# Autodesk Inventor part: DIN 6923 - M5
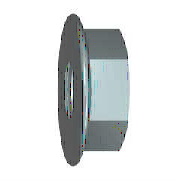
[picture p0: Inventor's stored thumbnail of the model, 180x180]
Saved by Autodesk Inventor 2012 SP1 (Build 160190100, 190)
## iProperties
Created: 2006-02
Part Number: DIN 6923 - M5
Material: Steel, Mild
Description: Hex Nut
Document SubType Name: Modeling
Standard: DIN 6923
Standards Organization: DIN
Language: en-US
Size Designation: M5
Categories: <MemberInstance><Categories><Category DisplayName="Fasteners" InternalName="e4da775c-781d-43d5-af7c-5136215cf5a6" Mnemonic="FSTN"><Category DisplayName="Nuts" I
Mass: 2.39626 g
Surface Area: 3.69972 cm^2
Volume: 0.304867 cm^3
Density: 7.86 g/cm^3
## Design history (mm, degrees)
workaxis "Work Axis1"
workplane "Work Plane1"
revolve "Ring" stored, may be unused: angle "d8" = 90 deg
sketch "Sketch2"
  geometry: L1 (-4, -2.309)-(-4, 2.309); L2 (-4, 2.309)-(0, 4.619); L3 (0, 4.619)-(4, 2.309); L4 (4, 2.309)-(4, -2.309); L5 (4, -2.309)-(0, -4.619); L6 (0, -4.619)-(-4, -2.309); C1 r 4.9 at (0, 0); C2 r 4.9 at (0, 0) reference; 1 further point
  constraints: 12 end point, 1 centre point, 1 coincident, 1 vertical, 11 other
  dimensions: "d6" = 9.2376 distance of L5.end L2.end (= 1.1547 x SW)
extrude "Body" join sketch "Sketch2" distance "d7" = 5 (= KOH); taper "d9" = 0 deg
revolve "Chamfer1" stored, may be unused: angle "d24" = 90 deg
sketch "Sketch4"
  geometry: C1 r 4.9 at (0, 0) reference; 1 further point
  constraints: 1 coincident
hole "Thread" sketch "Sketch4" diameter "d25" = 4.134; stored, may be unused: countersink angle "d29" = 82 deg, drill point angle "d31" = 118 deg; dims "d26" = 6, "d27" = 4, "d28" = 2, "d30" = 8
body "Solid1"
chamfer "Chamfer2" distance "d12" = 0.43301 (= -0.5 x GD1 + 0.5 x NND); stored, may be unused: angle "d13" = 30 deg, second distance "d46" = 0.43301 (= -0.5 x GD1 + 0.5 x NND)
chamfer "Chamfer3" distance "d51" = 0.43301 (= -0.5 x GD1 + 0.5 x NND); stored, may be unused: second distance "d52" = 2, angle "d53" = 45 deg
sketch "Sketch1"
  geometry: L1 (-0.687, 0)-(6.551, 0) reference; L2 (2.235, 4.619)-(1.906, 5.323); L3 (2.235, 4.619)-(5, 4.619); L4 (5, 4.619)-(5, 0); L5 (2.235, 4.619)-(2.235, 0); L6 (0, -0.609)-(0, 7.914) reference; A1 r 1 centre (1, 4.9) between (1.906, 5.323) and (0, 4.9); 1 further point
  constraints: 8 end point, 3 point on line, 2 perpendicular, 2 point on circle, 2 tangent, 1 centre point, 1 parallel
  dimensions: "d2" = 9.2376 diameter of L3 L1 (= 1.1547 x SW); "d4" = 11.8 dimension on A1 L1 (= LADI); "d5" = 1 radius of A1 (= PHH); "d15" = 5 distance between parallel lines of L4 L6 (= KOH); "d16" = 25 deg angle of L6 L2 (= KEWI)
sketch "Sketch3"
  geometry: L1 (2.235, 4.619)-(5, 4.619) reference; L2 (5, 2.309)-(5, 4.619) reference; L3 (0, -4.9)-(0, 4.9) reference; L4 (-0.5, 0)-(6.5, 0) reference; L5 (4.834, 4.619)-(5, 4)
  constraints: 2 end point, 2 point on line
  dimensions: "d10" = 15 deg angle of L2 L5 (= ANG1); "d11" = 8 diameter of L5.end L4 (= SW0)
other parameters: "ANG1" = 15 deg [user parameter; used in 1 equation term], "KEWI" = 25 deg [user parameter; used in 1 equation term], "NND" = 5 [user parameter; used in 4 equation terms], "LADI" = 11.8 [user parameter; used in 2 equation terms], "SW" = 8 [user parameter; used in 4 equation terms], "PHH" = 1 (= RR) [user parameter; used in 2 equation terms], "KOH" = 5 (= NND) [user parameter; used in 2 equation terms], "SW0" = 8 (= SW) [user parameter; used in 1 equation term], "GD1" = 4.13397 (computed from THREADDIA, PTC, TOA) [user parameter; used in 3 equation terms], "d1" = 11.8 (= LADI), "d3" = 1 (= PHH), "d45" = 0, "d47" = 0, "d49" = 0, "d54" = 0, "GUL" = 0.43301 (= 0.541266 x PTC) [user parameter], "TPU" = 12.5 (computed from PTC) [user parameter], "RR" = 1 [user parameter; used in 1 equation term], "THREADDIA" = 5 [user parameter; used in 1 equation term], "TOA" = 30 deg [user parameter; used in 1 equation term], "PTC" = 0.8 [user parameter; used in 4 equation terms], "GAL" = 0.43301 (= 0.541266 x PTC) [user parameter], "E0" = 9.24 (= 1.155 x SW) [user parameter]
